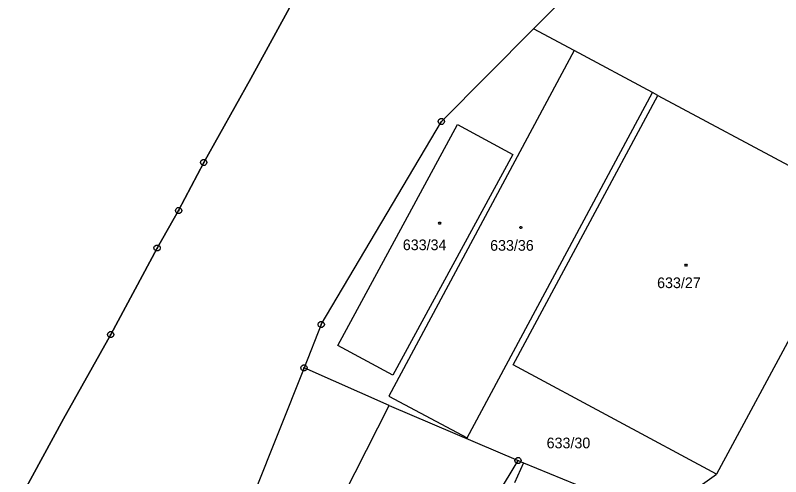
# Model space of a CAD drawing. Extents: x -759060 to -757386, y -1172273 to -1170948.
# Drawn here: x -758369.7 to -758247.7, y -1171369.6 to -1171296.1 of the extents above; entities that cross this region are included whole.
import ezdxf

# ---------------------------------------------------------------- set-up
doc = ezdxf.new("R2010")
doc.units = 0
for name, color, linetype in [('Vrstva 1', 7, 'Continuous'), ('Vrstva 11', 7, 'Continuous'), ('Vrstva 12', 7, 'Continuous'), ('Vrstva 2', 7, 'Continuous'), ('Vrstva 5', 7, 'Continuous'), ('Vrstva 8', 7, 'Continuous')]:
    doc.layers.add(name, color=color, linetype=linetype)

msp = doc.modelspace()

# ---------------------------------------------------------------- linework, layer by layer
at = {"layer": 'Vrstva 1'}
for p, q in [((-758324.71, -1171292.52), (-758332.15, -1171306.13)), ((-758280.68, -1171291.78), (-758287.08, -1171298.22)), ((-758287.08, -1171298.22), (-758301.77, -1171313.01)), ((-758280.61, -1171301.69), (-758287.08, -1171298.22)), ((-758280.61, -1171301.69), (-758310.15, -1171356.79)), ((-758268.13, -1171308.39), (-758280.61, -1171301.69)), ((-758332.15, -1171306.13), (-758339.63, -1171319.54)), ((-758297.69, -1171363.46), (-758268.13, -1171308.39)), ((-758267.3, -1171308.84), (-758268.13, -1171308.39)), ((-758290.36, -1171351.79), (-758267.3, -1171308.84)), ((-758267.3, -1171308.84), (-758234.85, -1171326.27)), ((-758320.92, -1171345.38), (-758301.77, -1171313.01)), ((-758318.26, -1171348.73), (-758299.21, -1171313.5)), ((-758299.21, -1171313.5), (-758290.41, -1171318.27)), ((-758290.41, -1171318.27), (-758309.5, -1171353.46)), ((-758339.63, -1171319.54), (-758343.64, -1171327.21)), ((-758234.85, -1171326.27), (-758257.96, -1171369.23)), ((-758343.64, -1171327.21), (-758347.06, -1171333.18)), ((-758347.06, -1171333.18), (-758354.46, -1171346.98)), ((-758320.92, -1171345.38), (-758323.66, -1171352.29)), ((-758354.46, -1171346.98), (-758361.97, -1171360.38)), ((-758309.5, -1171353.46), (-758318.26, -1171348.73)), ((-758323.66, -1171352.29), (-758334.67, -1171380)), ((-758310.09, -1171358.28), (-758323.66, -1171352.29)), ((-758257.96, -1171369.23), (-758290.36, -1171351.79)), ((-758310.15, -1171356.79), (-758297.69, -1171363.46)), ((-758324.43, -1171386.38), (-758310.09, -1171358.28)), ((-758310.09, -1171358.28), (-758289.56, -1171367.06)), ((-758361.97, -1171360.38), (-758369.66, -1171374.49)), ((-758306.01, -1171394.17), (-758289.56, -1171367.06)), ((-758289.56, -1171367.06), (-758288.68, -1171367.44)), ((-758288.68, -1171367.44), (-758290.15, -1171370.6)), ((-758288.68, -1171367.44), (-758274.95, -1171373.03)), ((-758271.03, -1171378.52), (-758257.96, -1171369.23))]:
    msp.add_line(p, q, dxfattribs=at)
at = {"layer": 'Vrstva 11'}
for p, q in [((-758332.15, -1171306.13), (-758324.71, -1171292.52)), ((-758339.63, -1171319.54), (-758332.15, -1171306.13)), ((-758343.64, -1171327.21), (-758339.63, -1171319.54)), ((-758347.06, -1171333.18), (-758343.64, -1171327.21)), ((-758354.46, -1171346.98), (-758347.06, -1171333.18)), ((-758361.97, -1171360.38), (-758354.46, -1171346.98)), ((-758369.66, -1171374.49), (-758361.97, -1171360.38))]:
    msp.add_line(p, q, dxfattribs=at)
at = {"layer": 'Vrstva 12'}
for p, q in [((-758280.61, -1171301.69), (-758310.15, -1171356.79)), ((-758268.13, -1171308.39), (-758280.61, -1171301.69)), ((-758297.69, -1171363.46), (-758268.13, -1171308.39)), ((-758290.36, -1171351.79), (-758267.3, -1171308.84)), ((-758267.3, -1171308.84), (-758234.85, -1171326.27)), ((-758318.26, -1171348.73), (-758299.21, -1171313.5)), ((-758299.21, -1171313.5), (-758290.41, -1171318.27)), ((-758290.41, -1171318.27), (-758309.5, -1171353.46)), ((-758234.85, -1171326.27), (-758257.96, -1171369.23)), ((-758309.5, -1171353.46), (-758318.26, -1171348.73)), ((-758257.96, -1171369.23), (-758290.36, -1171351.79)), ((-758310.15, -1171356.79), (-758297.69, -1171363.46))]:
    msp.add_line(p, q, dxfattribs=at)
at = {"layer": 'Vrstva 5'}
for points in [[(-758301.96, -1171329.05), (-758301.87, -1171329.2), (-758301.96, -1171329.35), (-758302.14, -1171329.35), (-758302.23, -1171329.2), (-758302.14, -1171329.05)], [(-758289.03, -1171329.77), (-758288.94, -1171329.92), (-758289.03, -1171330.07), (-758289.21, -1171330.07), (-758289.3, -1171329.92), (-758289.21, -1171329.77)], [(-758262.7, -1171335.75), (-758262.61, -1171335.9), (-758262.7, -1171336.05), (-758262.88, -1171336.05), (-758262.97, -1171335.9), (-758262.88, -1171335.75)]]:
    msp.add_lwpolyline(points, close=True, dxfattribs=at)
at = {"layer": 'Vrstva 8'}
for p, q in [((-758301.89, -1171313.01), (-758301.65, -1171313.01)), ((-758339.75, -1171319.54), (-758339.51, -1171319.54)), ((-758343.76, -1171327.21), (-758343.52, -1171327.21)), ((-758347.18, -1171333.18), (-758346.94, -1171333.18)), ((-758321.04, -1171345.38), (-758320.8, -1171345.38)), ((-758354.58, -1171346.98), (-758354.34, -1171346.98)), ((-758323.78, -1171352.29), (-758323.54, -1171352.29)), ((-758289.68, -1171367.06), (-758289.44, -1171367.06))]:
    msp.add_line(p, q, dxfattribs=at)
for points in [[(-758301.62, -1171312.53), (-758301.37, -1171312.71), (-758301.27, -1171313), (-758301.37, -1171313.29), (-758301.62, -1171313.47), (-758301.93, -1171313.47), (-758302.18, -1171313.29), (-758302.28, -1171313), (-758302.18, -1171312.71), (-758301.93, -1171312.53)], [(-758339.48, -1171319.06), (-758339.23, -1171319.24), (-758339.13, -1171319.53), (-758339.23, -1171319.82), (-758339.48, -1171320), (-758339.79, -1171320), (-758340.04, -1171319.82), (-758340.14, -1171319.53), (-758340.04, -1171319.24), (-758339.79, -1171319.06)], [(-758343.49, -1171326.73), (-758343.24, -1171326.91), (-758343.14, -1171327.2), (-758343.24, -1171327.49), (-758343.49, -1171327.67), (-758343.8, -1171327.67), (-758344.05, -1171327.49), (-758344.15, -1171327.2), (-758344.05, -1171326.91), (-758343.8, -1171326.73)], [(-758346.91, -1171332.7), (-758346.66, -1171332.88), (-758346.56, -1171333.17), (-758346.66, -1171333.46), (-758346.91, -1171333.64), (-758347.22, -1171333.64), (-758347.47, -1171333.46), (-758347.57, -1171333.17), (-758347.47, -1171332.88), (-758347.22, -1171332.7)], [(-758320.77, -1171344.9), (-758320.52, -1171345.08), (-758320.42, -1171345.37), (-758320.52, -1171345.66), (-758320.77, -1171345.84), (-758321.08, -1171345.84), (-758321.33, -1171345.66), (-758321.43, -1171345.37), (-758321.33, -1171345.08), (-758321.08, -1171344.9)], [(-758354.31, -1171346.5), (-758354.06, -1171346.68), (-758353.96, -1171346.97), (-758354.06, -1171347.26), (-758354.31, -1171347.44), (-758354.62, -1171347.44), (-758354.87, -1171347.26), (-758354.97, -1171346.97), (-758354.87, -1171346.68), (-758354.62, -1171346.5)], [(-758323.51, -1171351.81), (-758323.26, -1171351.99), (-758323.16, -1171352.28), (-758323.26, -1171352.57), (-758323.51, -1171352.75), (-758323.82, -1171352.75), (-758324.07, -1171352.57), (-758324.17, -1171352.28), (-758324.07, -1171351.99), (-758323.82, -1171351.81)], [(-758289.41, -1171366.58), (-758289.16, -1171366.76), (-758289.06, -1171367.05), (-758289.16, -1171367.34), (-758289.41, -1171367.52), (-758289.72, -1171367.52), (-758289.97, -1171367.34), (-758290.07, -1171367.05), (-758289.97, -1171366.76), (-758289.72, -1171366.58)]]:
    msp.add_lwpolyline(points, close=True, dxfattribs=at)

# ---------------------------------------------------------------- texts
at = {"layer": 'Vrstva 2'}
for s, p in [('633/34', (-758307.924, -1171333.52)), ('633/36', (-758294.014, -1171333.61)), ('633/27', (-758267.41, -1171339.57)), ('633/30', (-758285.01, -1171365.1))]:
    msp.add_text(s, height=1.7, dxfattribs=at).set_placement(p)

doc.saveas('drawing.dxf')
